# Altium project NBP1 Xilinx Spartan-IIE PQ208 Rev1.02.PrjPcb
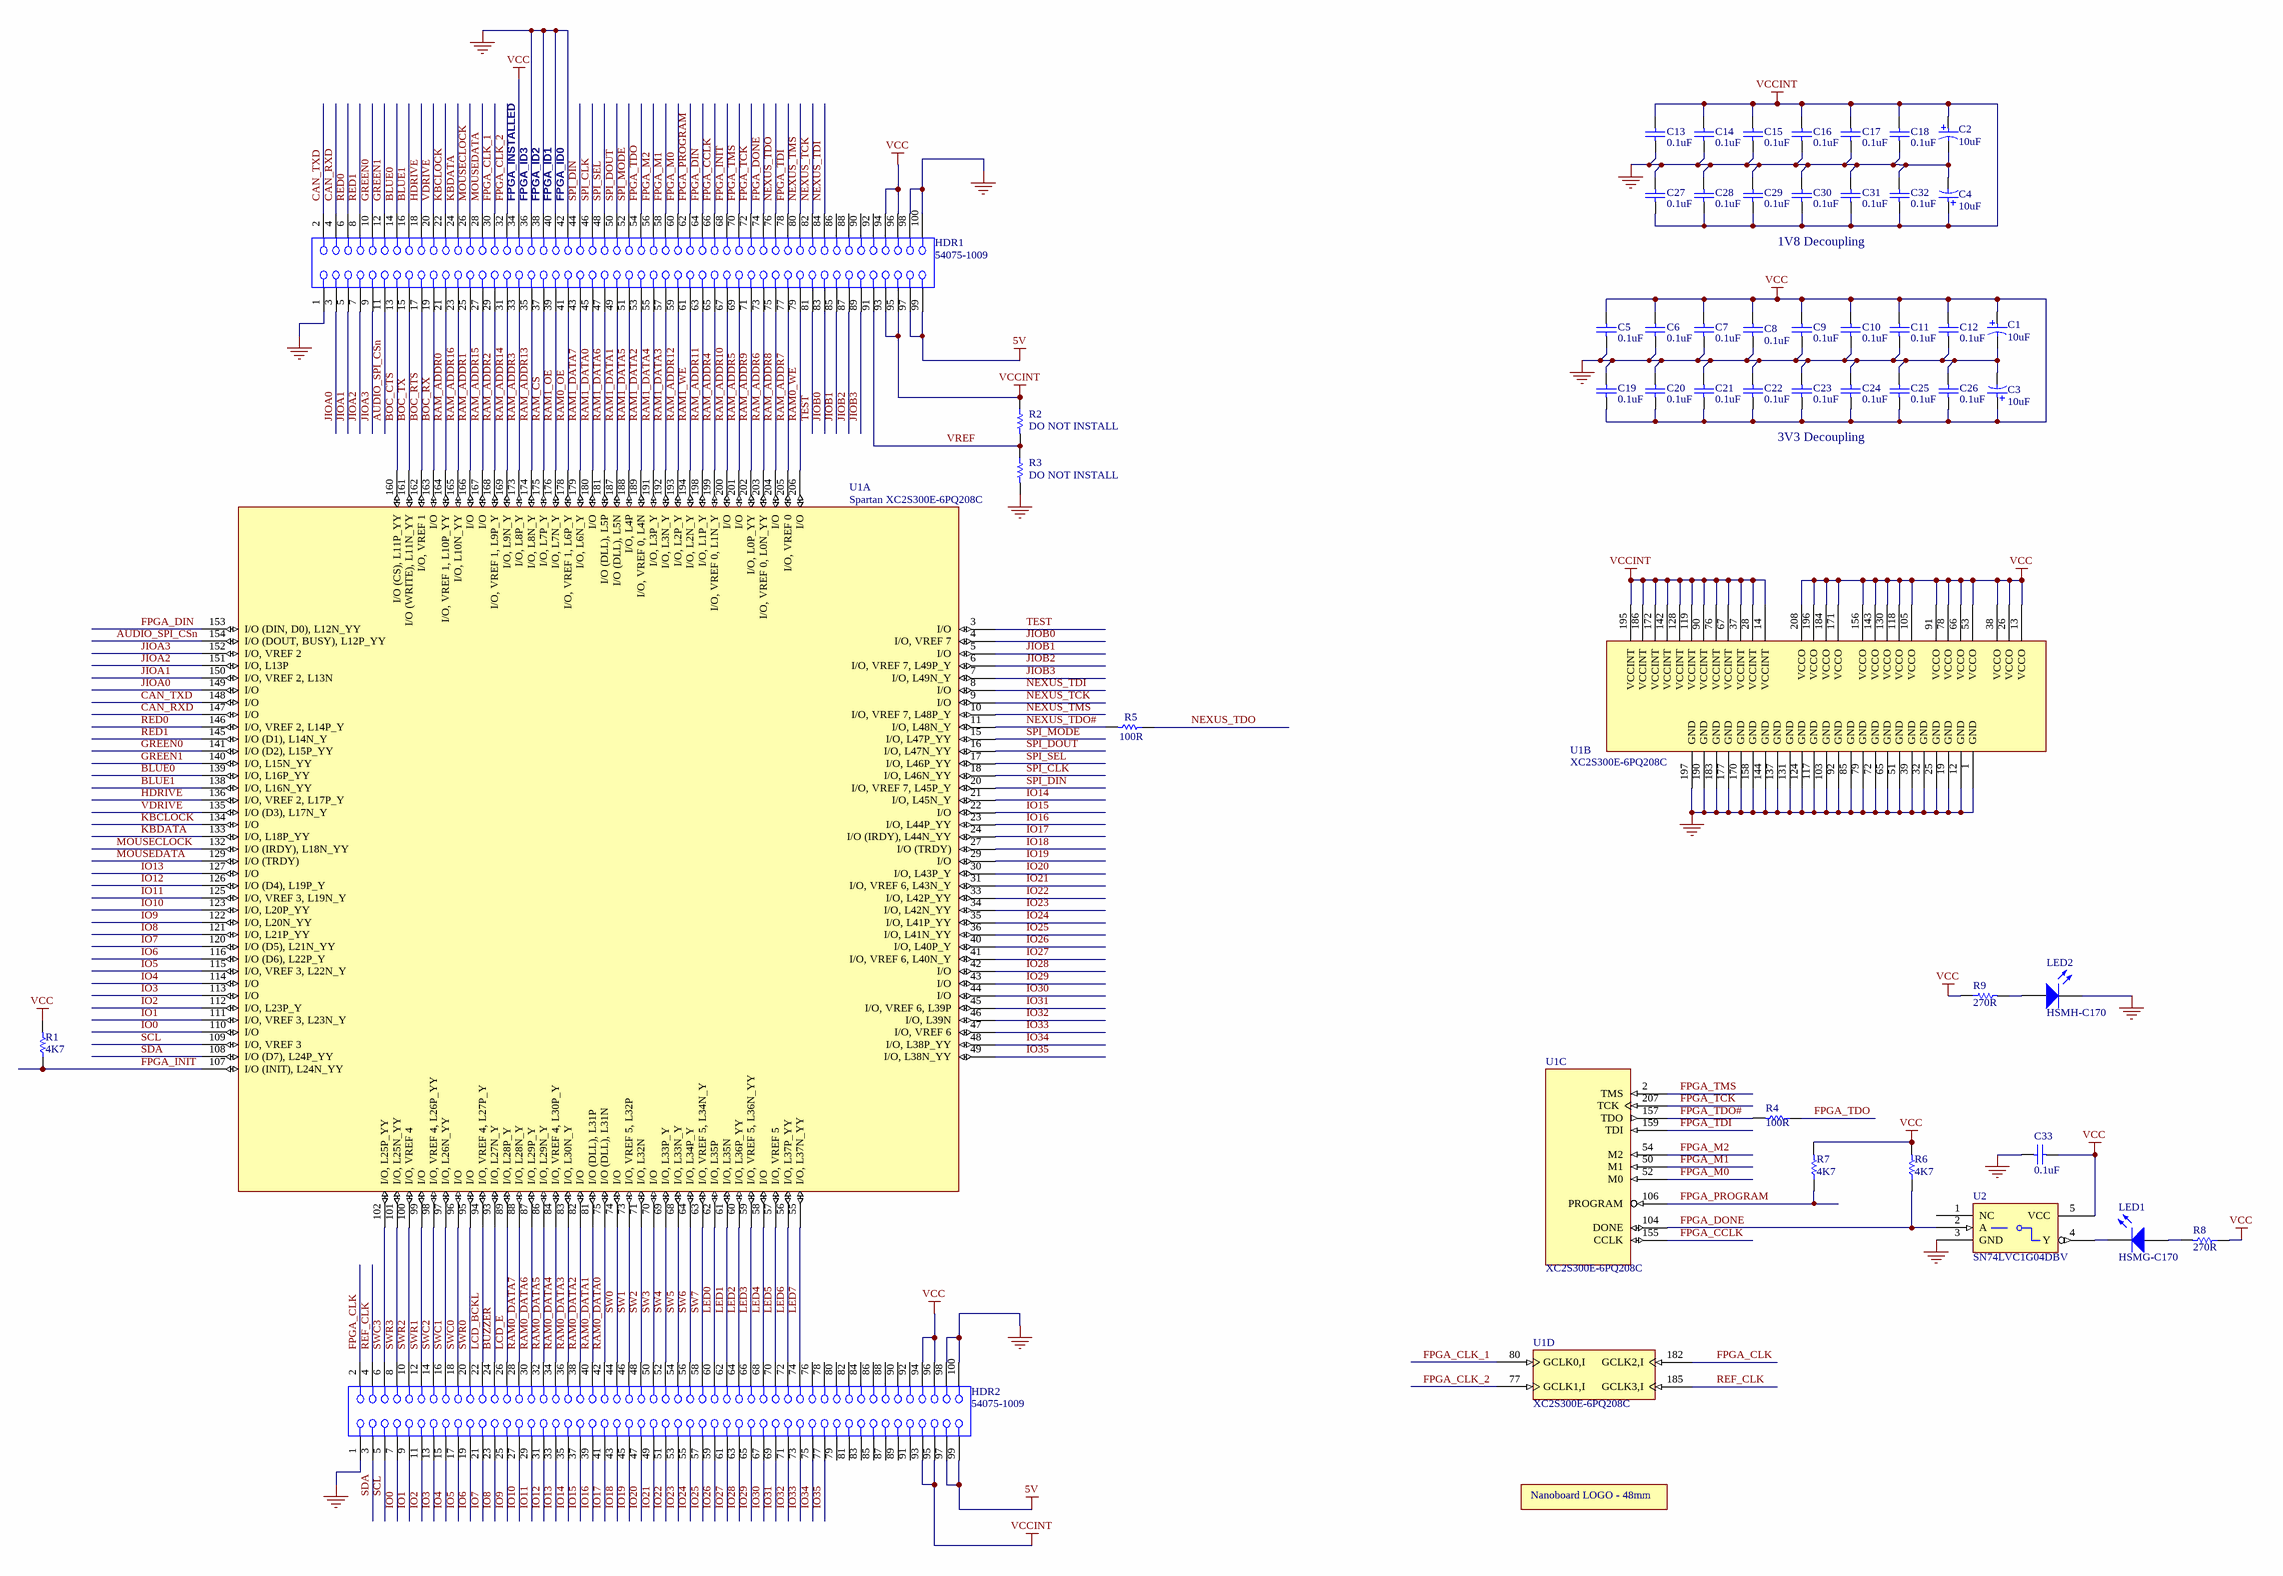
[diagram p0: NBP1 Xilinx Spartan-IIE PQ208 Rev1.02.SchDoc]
1 sheet, 49 parts. Net scope: global (net labels, ports and power ports of the same name join across sheets).
Board file: NBP1 Xilinx Spartan-IIE PQ208 Rev1.02.PcbDoc

## Sheet NBP1 Xilinx Spartan-IIE PQ208 Rev1.02.SchDoc: Spartan 2E 300 Daughterboard
size C; Organization: Altium Limited; Address1: L3, 12a Rodborough Rd; Address2: Frenchs Forest; Address3: NSW; Address4: Australia 2086; DocumentNumber: 1; Revision: 1.02; SheetNumber: 1; SheetTotal: 1

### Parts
?  NanoboardLogo48mm  [NanoBoard1_LOGO]  (value not drawn)  (graphical)
C1  10uF  [MCCT-B]
C2  10uF  [MCCT-B]
C3  10uF  [MCCT-B]
C4  10uF  [MCCT-B]
C5  0.1uF  [CC2012-0805]
C6  0.1uF  [CC2012-0805]
C7  0.1uF  [CC2012-0805]
C8  0.1uF  [CC2012-0805]
C9  0.1uF  [CC2012-0805]
C10  0.1uF  [CC2012-0805]
C11  0.1uF  [CC2012-0805]
C12  0.1uF  [CC2012-0805]
C13  0.1uF  [CC2012-0805]
C14  0.1uF  [CC2012-0805]
C15  0.1uF  [CC2012-0805]
C16  0.1uF  [CC2012-0805]
C17  0.1uF  [CC2012-0805]
C18  0.1uF  [CC2012-0805]
C19  0.1uF  [CC2012-0805]
C20  0.1uF  [CC2012-0805]
C21  0.1uF  [CC2012-0805]
C22  0.1uF  [CC2012-0805]
C23  0.1uF  [CC2012-0805]
C24  0.1uF  [CC2012-0805]
C25  0.1uF  [CC2012-0805]
C26  0.1uF  [CC2012-0805]
C27  0.1uF  [CC2012-0805]
C28  0.1uF  [CC2012-0805]
C29  0.1uF  [CC2012-0805]
C30  0.1uF  [CC2012-0805]
C31  0.1uF  [CC2012-0805]
C32  0.1uF  [CC2012-0805]
C33  0.1uF  [CC2012-0805]
HDR1  54075-1009  [54075]
HDR2  54075-1009  [54075]
LED1  HSMG-C170  [SMD _LED]
LED2  HSMH-C170  [SMD _LED]
R1  4K7  [CC2012-0805]
R2  DO NOT INSTALL  [CC2012-0805]
R3  DO NOT INSTALL  [CC2012-0805]
R4  100R  [CC2012-0805]
R5  100R  [CC2012-0805]
R6  4K7  [CC2012-0805]
R7  4K7  [CC2012-0805]
R8  270R  [CC2012-0805]
R9  270R  [CC2012-0805]
U1  Spartan XC2S300E-6PQ208C  [F-QFP28x28-G208/P.5N]  (parts A,B,C,D of 4)
U2  SN74LVC1G04DBV  [SO-G5/P.95]

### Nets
5V: HDR1.97 HDR1.99 HDR2.97 HDR2.99
GND: C1.2 C2.2 C3.2 C4.2 C5.1 C6.1 C7.1 C8.1 C9.1 C10.1 C11.1 C12.1 C13.1 C14.1 C15.1 C16.1 C17.1 C18.1 C19.2 C20.2 C21.2 C22.2 C23.2 C24.2 C25.2 C26.2 C27.2 C28.2 C29.2 C30.2 C31.2 C32.2 C33.2 HDR1.1 HDR1.36 HDR1.38 HDR1.40 HDR1.42 HDR1.98 HDR1.100 HDR2.1 HDR2.98 HDR2.100 LED2.2(K) R3.2 U1.1(GND) U1.12(GND) U1.19(GND) U1.25(GND) U1.32(GND) U1.39(GND) U1.51(GND) U1.65(GND) U1.72(GND) U1.79(GND) U1.85(GND) U1.92(GND) U1.103(GND) U1.117(GND) U1.124(GND) U1.131(GND) U1.137(GND) U1.144(GND) U1.158(GND) U1.170(GND) U1.177(GND) U1.183(GND) U1.190(GND) U1.197(GND) U2.3(GND)
VCC: C1.1 C3.1 C5.2 C6.2 C7.2 C8.2 C9.2 C10.2 C11.2 C12.2 C19.1 C20.1 C21.1 C22.1 C23.1 C24.1 C25.1 C26.1 C33.1 HDR1.34 HDR1.94 HDR1.96 HDR2.94 HDR2.96 R1.2 R6.2 R7.2 R8.1 R9.1 U1.13(VCCO) U1.26(VCCO) U1.38(VCCO) U1.53(VCCO) U1.66(VCCO) U1.78(VCCO) U1.91(VCCO) U1.105(VCCO) U1.118(VCCO) U1.130(VCCO) U1.143(VCCO) U1.156(VCCO) U1.171(VCCO) U1.184(VCCO) U1.196(VCCO) U1.208(VCCO) U2.5(VCC)
VCCINT: C2.1 C4.1 C13.2 C14.2 C15.2 C16.2 C17.2 C18.2 C27.1 C28.1 C29.1 C30.1 C31.1 C32.1 HDR1.93 HDR1.95 HDR2.93 HDR2.95 R2.1 U1.14(VCCINT) U1.28(VCCINT) U1.37(VCCINT) U1.67(VCCINT) U1.76(VCCINT) U1.90(VCCINT) U1.119(VCCINT) U1.128(VCCINT) U1.142(VCCINT) U1.172(VCCINT) U1.186(VCCINT) U1.195(VCCINT)
AUDIO_SPI_CSn: HDR1.11 U1.154(I/O_(DOUT,_BUSY),_L12P_YY)
BLUE0: HDR1.14 U1.139(I/O,_L16P_YY)
BLUE1: HDR1.16 U1.138(I/O,_L16N_YY)
BOC_CTS: HDR1.13 U1.160(I/O_(CS),_L11P_YY)
BOC_RTS: HDR1.17 U1.162(I/O,_VREF_1)
BOC_RX: HDR1.19 U1.163(I/O)
BOC_TX: HDR1.15 U1.161(I/O_(WRITE),_L11N_YY)
BUZZER: HDR2.24 U1.93(I/O,_L27N_Y)
CAN_RXD: HDR1.4 U1.147(I/O)
CAN_TXD: HDR1.2 U1.148(I/O)
FPGA_CCLK: HDR1.66 U1.155(CCLK)
FPGA_CLK: HDR2.2 U1.182(GCLK2,I)
FPGA_CLK_1: HDR1.30 U1.80(GCLK0,I)
FPGA_CLK_2: HDR1.32 U1.77(GCLK1,I)
FPGA_DIN: HDR1.64 U1.153(I/O_(DIN,_D0),_L12N_YY)
FPGA_DONE: HDR1.74 R6.1 U1.104(DONE) U2.2(A)
FPGA_INIT: HDR1.68 R1.1 U1.107(I/O_(INIT),_L24N_YY)
FPGA_M0: HDR1.60 U1.52(M0)
FPGA_M1: HDR1.58 U1.50(M1)
FPGA_M2: HDR1.56 U1.54(M2)
FPGA_PROGRAM: HDR1.62 R7.1 U1.106(PROGRAM)
FPGA_TCK: HDR1.72 U1.207(TCK)
FPGA_TDI: HDR1.78 U1.159(TDI)
FPGA_TDO: HDR1.54 R4.1
FPGA_TDO#: R4.2 U1.157(TDO)
FPGA_TMS: HDR1.70 U1.2(TMS)
GREEN0: HDR1.10 U1.141(I/O_(D2),_L15P_YY)
GREEN1: HDR1.12 U1.140(I/O,_L15N_YY)
HDRIVE: HDR1.18 U1.136(I/O,_VREF_2,_L17P_Y)
IO0: HDR2.7 U1.110(I/O)
IO1: HDR2.9 U1.111(I/O,_VREF_3,_L23N_Y)
IO2: HDR2.11 U1.112(I/O,_L23P_Y)
IO3: HDR2.13 U1.113(I/O)
IO4: HDR2.15 U1.114(I/O)
IO5: HDR2.17 U1.115(I/O,_VREF_3,_L22N_Y)
IO6: HDR2.19 U1.116(I/O_(D6),_L22P_Y)
IO7: HDR2.21 U1.120(I/O_(D5),_L21N_YY)
IO8: HDR2.23 U1.121(I/O,_L21P_YY)
IO9: HDR2.25 U1.122(I/O,_L20N_YY)
IO10: HDR2.27 U1.123(I/O,_L20P_YY)
IO11: HDR2.29 U1.125(I/O,_VREF_3,_L19N_Y)
IO12: HDR2.31 U1.126(I/O_(D4),_L19P_Y)
IO13: HDR2.33 U1.127(I/O)
IO14: HDR2.35 U1.21(I/O,_L45N_Y)
IO15: HDR2.37 U1.22(I/O)
IO16: HDR2.39 U1.23(I/O,_L44P_YY)
IO17: HDR2.41 U1.24(I/O_(IRDY),_L44N_YY)
IO18: HDR2.43 U1.27(I/O_(TRDY))
IO19: HDR2.45 U1.29(I/O)
IO20: HDR2.47 U1.30(I/O,_L43P_Y)
IO21: HDR2.49 U1.31(I/O,_VREF_6,_L43N_Y)
IO22: HDR2.51 U1.33(I/O,_L42P_YY)
IO23: HDR2.53 U1.34(I/O,_L42N_YY)
IO24: HDR2.55 U1.35(I/O,_L41P_YY)
IO25: HDR2.57 U1.36(I/O,_L41N_YY)
IO26: HDR2.59 U1.40(I/O,_L40P_Y)
IO27: HDR2.61 U1.41(I/O,_VREF_6,_L40N_Y)
IO28: HDR2.63 U1.42(I/O)
IO29: HDR2.65 U1.43(I/O)
IO30: HDR2.67 U1.44(I/O)
IO31: HDR2.69 U1.45(I/O,_VREF_6,_L39P)
IO32: HDR2.71 U1.46(I/O,_L39N)
IO33: HDR2.73 U1.47(I/O,_VREF_6)
IO34: HDR2.75 U1.48(I/O,_L38P_YY)
IO35: HDR2.77 U1.49(I/O,_L38N_YY)
JIOA0: HDR1.3 U1.149(I/O)
JIOA1: HDR1.5 U1.150(I/O,_VREF_2,_L13N)
JIOA2: HDR1.7 U1.151(I/O,_L13P)
JIOA3: HDR1.9 U1.152(I/O,_VREF_2)
JIOB0: HDR1.83 U1.4(I/O,_VREF_7)
JIOB1: HDR1.85 U1.5(I/O)
JIOB2: HDR1.87 U1.6(I/O,_VREF_7,_L49P_Y)
JIOB3: HDR1.89 U1.7(I/O,_L49N_Y)
KBCLOCK: HDR1.22 U1.134(I/O)
KBDATA: HDR1.24 U1.133(I/O,_L18P_YY)
LCD_BCKL: HDR2.22 U1.94(I/O,_VREF_4,_L27P_Y)
LCD_E: HDR2.26 U1.89(I/O,_L28P_Y)
LED0: HDR2.60 U1.62(I/O,_L35P)
LED1: HDR2.62 U1.61(I/O,_L35N)
LED2: HDR2.64 U1.60(I/O,_L36P_YY)
LED3: HDR2.66 U1.59(I/O,_VREF_5,_L36N_YY)
LED4: HDR2.68 U1.58(I/O)
LED5: HDR2.70 U1.57(I/O,_VREF_5)
LED6: HDR2.72 U1.56(I/O,_L37P_YY)
LED7: HDR2.74 U1.55(I/O,_L37N_YY)
MOUSECLOCK: HDR1.26 U1.132(I/O_(IRDY),_L18N_YY)
MOUSEDATA: HDR1.28 U1.129(I/O_(TRDY))
NEXUS_TCK: HDR1.82 U1.9(I/O)
NEXUS_TDI: HDR1.84 U1.8(I/O)
NEXUS_TDO: HDR1.76 R5.1
NEXUS_TDO#: R5.2 U1.11(I/O,_L48N_Y)
NEXUS_TMS: HDR1.80 U1.10(I/O,_VREF_7,_L48P_Y)
RAM0_DATA0: HDR2.42 U1.75(I/O_(DLL),_L31N)
RAM0_DATA1: HDR2.40 U1.81(I/O_(DLL),_L31P)
RAM0_DATA2: HDR2.38 U1.82(I/O)
RAM0_DATA3: HDR2.36 U1.83(I/O,_L30N_Y)
RAM0_DATA4: HDR2.34 U1.84(I/O,_VREF_4,_L30P_Y)
RAM0_DATA5: HDR2.32 U1.86(I/O,_L29N_Y)
RAM0_DATA6: HDR2.30 U1.87(I/O,_L29P_Y)
RAM0_DATA7: HDR2.28 U1.88(I/O,_L28N_Y)
RAM0_OE: HDR1.41 U1.178(I/O,_VREF_1,_L6P_Y)
RAM0_WE: HDR1.79 U1.206(I/O)
RAM1_DATA0: HDR1.45 U1.180(I/O)
RAM1_DATA1: HDR1.49 U1.187(I/O_(DLL),_L5N)
RAM1_DATA2: HDR1.53 U1.189(I/O,_VREF_0,_L4N)
RAM1_DATA3: HDR1.57 U1.192(I/O,_L3N_Y)
RAM1_DATA4: HDR1.55 U1.191(I/O,_L3P_Y)
RAM1_DATA5: HDR1.51 U1.188(I/O,_L4P)
RAM1_DATA6: HDR1.47 U1.181(I/O_(DLL),_L5P)
RAM1_DATA7: HDR1.43 U1.179(I/O,_L6N_Y)
RAM1_OE: HDR1.39 U1.176(I/O,_L7N_Y)
RAM1_WE: HDR1.61 U1.194(I/O,_L2N_Y)
RAM_ADDR0: HDR1.21 U1.164(I/O,_VREF_1,_L10P_YY)
RAM_ADDR1: HDR1.25 U1.166(I/O)
RAM_ADDR2: HDR1.29 U1.168(I/O,_VREF_1,_L9P_Y)
RAM_ADDR3: HDR1.33 U1.173(I/O,_L8P_Y)
RAM_ADDR4: HDR1.65 U1.199(I/O,_VREF_0,_L1N_Y)
RAM_ADDR5: HDR1.69 U1.201(I/O)
RAM_ADDR6: HDR1.73 U1.203(I/O,_VREF_0,_L0N_YY)
RAM_ADDR7: HDR1.77 U1.205(I/O,_VREF_0)
RAM_ADDR8: HDR1.75 U1.204(I/O)
RAM_ADDR9: HDR1.71 U1.202(I/O,_L0P_YY)
RAM_ADDR10: HDR1.67 U1.200(I/O)
RAM_ADDR11: HDR1.63 U1.198(I/O,_L1P_Y)
RAM_ADDR12: HDR1.59 U1.193(I/O,_L2P_Y)
RAM_ADDR13: HDR1.35 U1.174(I/O,_L8N_Y)
RAM_ADDR14: HDR1.31 U1.169(I/O,_L9N_Y)
RAM_ADDR15: HDR1.27 U1.167(I/O)
RAM_ADDR16: HDR1.23 U1.165(I/O,_L10N_YY)
RAM_CS: HDR1.37 U1.175(I/O,_L7P_Y)
RED0: HDR1.6 U1.146(I/O,_VREF_2,_L14P_Y)
RED1: HDR1.8 U1.145(I/O_(D1),_L14N_Y)
REF_CLK: HDR2.4 U1.185(GCLK3,I)
SCL: HDR2.5 U1.109(I/O,_VREF_3)
SDA: HDR2.3 U1.108(I/O_(D7),_L24P_YY)
SPI_CLK: HDR1.46 U1.18(I/O,_L46N_YY)
SPI_DIN: HDR1.44 U1.20(I/O,_VREF_7,_L45P_Y)
SPI_DOUT: HDR1.50 U1.16(I/O,_L47N_YY)
SPI_MODE: HDR1.52 U1.15(I/O,_L47P_YY)
SPI_SEL: HDR1.48 U1.17(I/O,_L46P_YY)
SW0: HDR2.44 U1.74(I/O)
SW1: HDR2.46 U1.73(I/O,_VREF_5,_L32P)
SW2: HDR2.48 U1.71(I/O,_L32N)
SW3: HDR2.50 U1.70(I/O)
SW4: HDR2.52 U1.69(I/O,_L33P_Y)
SW5: HDR2.54 U1.68(I/O,_L33N_Y)
SW6: HDR2.56 U1.64(I/O,_L34P_Y)
SW7: HDR2.58 U1.63(I/O,_VREF_5,_L34N_Y)
SWC0: HDR2.18 U1.96(I/O)
SWC1: HDR2.16 U1.97(I/O,_L26N_YY)
SWC2: HDR2.14 U1.98(I/O,_VREF_4,_L26P_YY)
SWC3: HDR2.6 U1.102(I/O,_L25P_YY)
SWR0: HDR2.20 U1.95(I/O)
SWR1: HDR2.12 U1.99(I/O)
SWR2: HDR2.10 U1.100(I/O,_VREF_4)
SWR3: HDR2.8 U1.101(I/O,_L25N_YY)
TEST: HDR1.81 U1.3(I/O)
VDRIVE: HDR1.20 U1.135(I/O_(D3),_L17N_Y)
VREF: HDR1.91 R2.2 R3.1
NetLED1_1: LED1.1(A) R8.2
NetLED1_2: LED1.2(K) U2.4(Y)
NetLED2_1: LED2.1(A) R9.2

Not connected (* = marked no-connect by the designer): HDR1 86 88 90 92; HDR2 76 78 79 80 81 82 83 84 85 86 87 88 89 90 91 92; U2 1(NC)

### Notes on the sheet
- (near HDR1) FPGA_INSTALLED
- (near HDR1) FPGA_ID3
- (near HDR1) FPGA_ID2
- (near HDR1) FPGA_ID1
- (near HDR1) FPGA_ID0
- 1V8 Decoupling
- 3V3 Decoupling

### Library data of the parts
C1-C4 = CAP_POLAR: Polar Capacitor
C5-C33 = CAP: Capacitor
HDR1 HDR2 = 54075-1009: Board-to-Board, Docking Station, 0.80mm (.031") Pitch, Shielded Receptacle, Vertical, Ultra Low Profile, SMT; Manufacturer: Molex; Package Information: Latest Revision: Jun-2001; Mating Height: 8.5mm; Voltage: 100V; Current: 0.5A; Contact Resistance: 40mOhm max; PCB Layout: Complies with Manufacturer's Recommendation.
LED1 LED2 = HSMX-C670: Typical RED GaAs SMD LED Agilent make; Manufacturer: Generic Components; Class I: Optoelectronic; Fitted: True
R1-R9 = RES: Resistor
U1 = XC2S300E-6PQ208I: 1.8V Field-Programmable Gate Array; Manufacturer: Xilinx; Package Information: Latest Revision: 1-Jun-2000; Class I: FPGA; Class II: Spartan-IIE
U2 = SN74AHC1G04DBVR: Manufacturer: TI; Fitted: True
